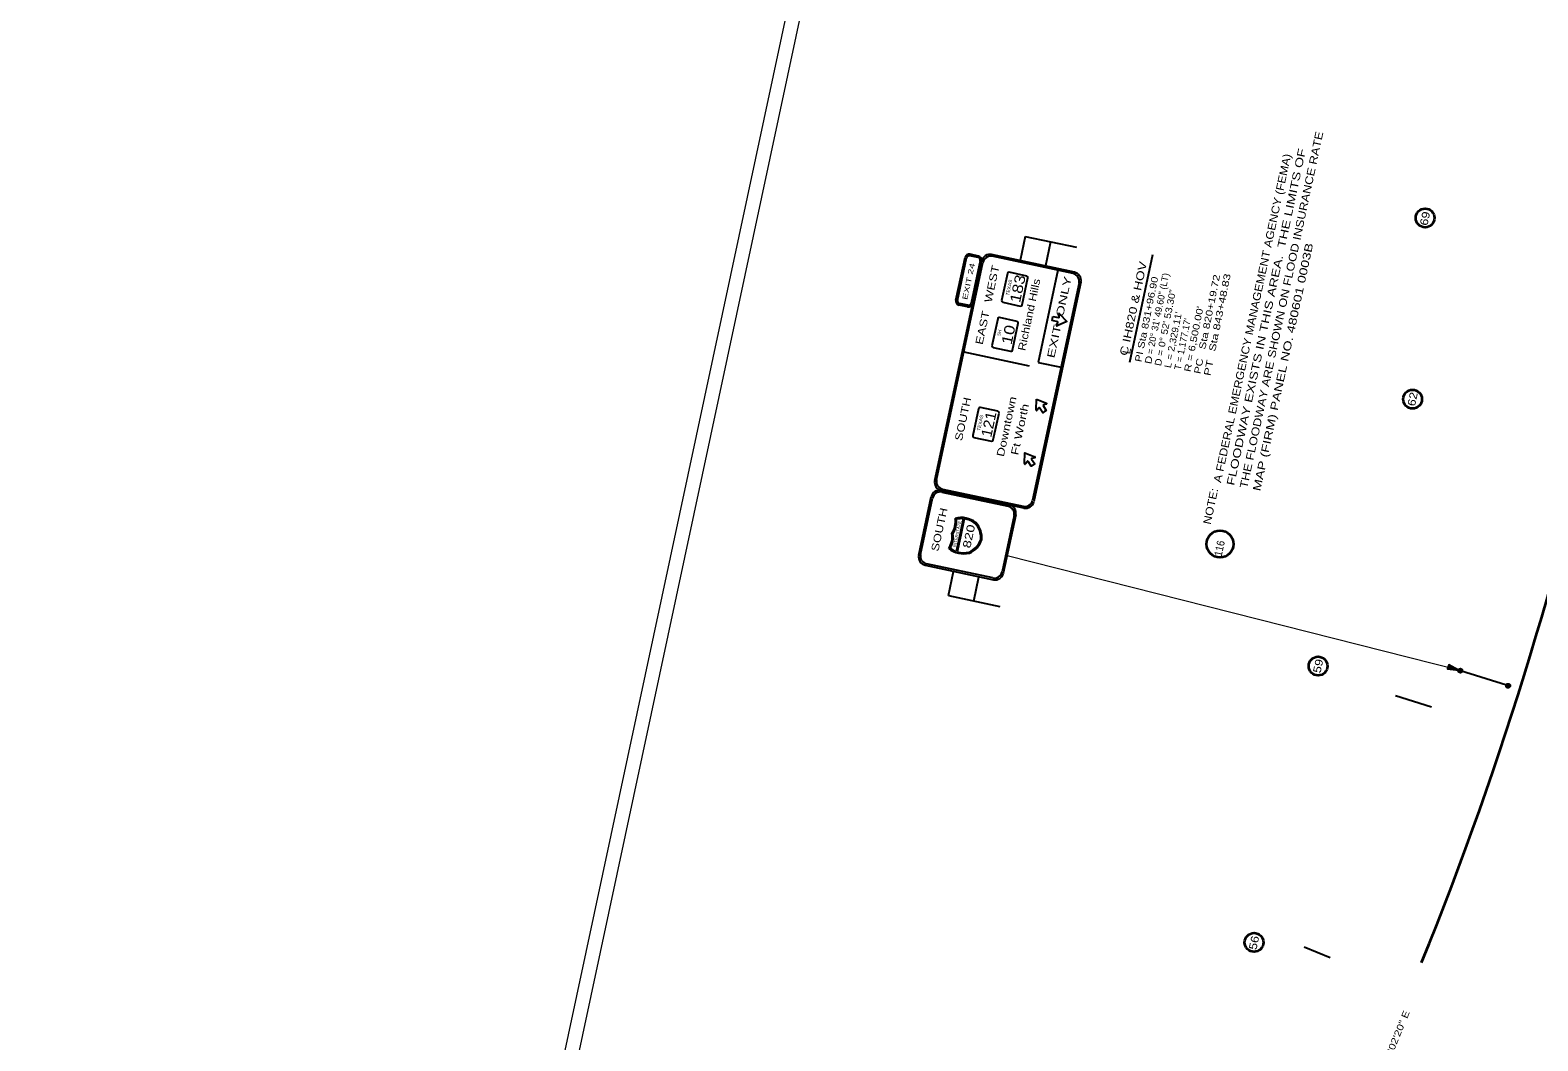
# Model space of a CAD drawing. Extents: x 2363411 to 2369702, y 6977197 to 6988655.
# Drawn here: x 2363411 to 2366110, y 6982449 to 6984259 of the extents above; entities that cross this region are included whole.
import ezdxf
from ezdxf.enums import TextEntityAlignment as Align

# ---------------------------------------------------------------- set-up
doc = ezdxf.new("R2010")
doc.units = 0
doc.header["$LTSCALE"] = 5.6
for name, color, linetype, lineweight in [('1', 7, 'Continuous', 25), ('10', 7, 'Continuous', 13), ('17', 7, 'Continuous', 35), ('23', 7, 'Continuous', 25), ('61', 7, 'Continuous', 25), ('63', 7, 'Continuous', 13)]:
    doc.layers.add(name, color=color, linetype=linetype, lineweight=lineweight)
doc.layers.add('28', color=7, linetype='Continuous')
doc.layers.add('33', color=7, linetype='Continuous')

msp = doc.modelspace()

# ---------------------------------------------------------------- hatches: boundary and pattern name
at = {"layer": '1'}
for points in [[(2365968.163, 6983113.023), (2365950.998, 6983122.363), (2365948.781, 6983115.505)], [(2365974.263, 6983114.727, 1), (2365969.018, 6983109.418, 1)], [(2366059.762, 6983087.598, 1), (2366054.517, 6983082.289, 1)]]:
    msp.add_hatch(color=256, dxfattribs=at).paths.add_polyline_path(points)

# ---------------------------------------------------------------- linework, layer by layer
for p, q in [((2365192.606, 6983889.962), (2365183.395, 6983846.56)), ((2365192.606, 6983889.962), (2365284.591, 6983870.44)), ((2365108.421, 6983851.96), (2365093.308, 6983855.189)), ((2365109.01, 6983854.715), (2365093.895, 6983857.943)), ((2365280.707, 6983825.698), (2365132.568, 6983857.342)), ((2365278.285, 6983823.345), (2365133.814, 6983854.209)), ((2365237.993, 6983880.329), (2365228.781, 6983836.928)), ((2365030.791, 6983452.71), (2365114.777, 6983845.811)), ((2365033.933, 6983453.956), (2365117.108, 6983843.396)), ((2365068.701, 6983775.889), (2365084.996, 6983852.178)), ((2365071.448, 6983775.301), (2365087.743, 6983851.588)), ((2365112.029, 6983846.397), (2365095.724, 6983770.116)), ((2365251.121, 6983829.148), (2365215.907, 6983664.282)), ((2365160.832, 6983823.37), (2365150.543, 6983775.227)), ((2365195.391, 6983818.863), (2365164.167, 6983825.536)), ((2365187.27, 6983767.379), (2365197.551, 6983815.521)), ((2365289.082, 6983806.645), (2365205.903, 6983417.213)), ((2365292.223, 6983807.899), (2365208.262, 6983414.792)), ((2365089.572, 6983763.755), (2365074.466, 6983766.99)), ((2365090.16, 6983766.51), (2365075.054, 6983769.739)), ((2365152.703, 6983771.884), (2365183.927, 6983765.219)), ((2365242.276, 6983746.531), (2365252.428, 6983744.361)), ((2365253.238, 6983745.131), (2365252.478, 6983750.601)), ((2365143.501, 6983742.231), (2365133.221, 6983694.081)), ((2365178.076, 6983737.733), (2365146.837, 6983744.404)), ((2365169.948, 6983686.24), (2365180.228, 6983734.39)), ((2365248.345, 6983731.255), (2365251.289, 6983735.953)), ((2365082.845, 6983682.972), (2365199.745, 6983657.991)), ((2365135.374, 6983690.745), (2365166.605, 6983684.074)), ((2365215.908, 6983664.282), (2365256.808, 6983655.541)), ((2365212.141, 6983579.098), (2365212.873, 6983598.247)), ((2365212.873, 6983598.247), (2365230.661, 6983591.091)), ((2365230.553, 6983589.15), (2365225.149, 6983587.91)), ((2365109.098, 6983581.22), (2365098.803, 6983533.063)), ((2365143.665, 6983576.699), (2365112.434, 6983583.379)), ((2365135.538, 6983525.214), (2365145.833, 6983573.365)), ((2365217.282, 6983582.799), (2365213.951, 6983578.393)), ((2365100.97, 6983529.727), (2365132.202, 6983523.047)), ((2365191.435, 6983483.155), (2365191.445, 6983483.193)), ((2365196.586, 6983486.894), (2365193.256, 6983482.489)), ((2365209.857, 6983493.246), (2365204.453, 6983492.005)), ((2365002.187, 6983318.803), (2365024.526, 6983423.366)), ((2365042.326, 6983434.91), (2365189.62, 6983403.437)), ((2365043.57, 6983431.763), (2365161.915, 6983406.478)), ((2365044.748, 6983437.271), (2365189.213, 6983406.399)), ((2365005.322, 6983320.048), (2365026.879, 6983420.944)), ((2365172.735, 6983389.787), (2365151.178, 6983288.892)), ((2365175.87, 6983391.025), (2365153.53, 6983286.47)), ((2365013.726, 6983301.005), (2365135.74, 6983274.931)), ((2365134.494, 6983278.073), (2365016.133, 6983303.357)), ((2365055.114, 6983246.485), (2365064.445, 6983289.861)), ((2365100.474, 6983236.729), (2365109.804, 6983280.105)), ((2365055.114, 6983246.485), (2365147.045, 6983226.711)), ((2365971.638, 6983112.084), (2366054.42, 6983086.496))]:
    msp.add_line(p, q, dxfattribs=at)
at = {"layer": '1', "lineweight": 13}
msp.add_line((2365968.163, 6983113.023), (2365160.255, 6983317.971), dxfattribs=at)
at = {"layer": '1'}
for points in [[(2365250.852, 6983736.972), (2365240.694, 6983739.133), (2365241.49, 6983742.817), (2365242.276, 6983746.531)], [(2365254.257, 6983751.382), (2365267.28, 6983737.324), (2365249.641, 6983729.807)], [(2365224.738, 6983586.88), (2365230.393, 6983578.17), (2365227.225, 6983576.126), (2365224.044, 6983574.055), (2365218.398, 6983582.77)], [(2365191.445, 6983483.193), (2365192.177, 6983502.342), (2365209.964, 6983495.185)], [(2365204.041, 6983490.975), (2365209.696, 6983482.264), (2365206.529, 6983480.221), (2365203.348, 6983478.151), (2365197.703, 6983486.865)], [(2365081.818, 6983384.265), (2365075.56, 6983354.922), (2365069.278, 6983325.591)], [(2365083.709, 6983384.062), (2365077.402, 6983354.527), (2365071.102, 6983325.008)]]:
    msp.add_lwpolyline(points, dxfattribs=at)
msp.add_lwpolyline([(2365968.163, 6983113.023), (2365950.998, 6983122.363), (2365948.781, 6983115.505)], close=True, dxfattribs=at)
for centre in [(2365971.641, 6983112.073), (2366057.139, 6983084.944)]:
    msp.add_circle(centre, 3.732, dxfattribs=at)
at = {"layer": '1', "lineweight": 35}
msp.add_arc((2359877.328, 6985028.058), 6500, 337.9611, 358.49155, dxfattribs=at)
at = {"layer": '1'}
for centre, radius, start, end in [((2365092.331, 6983850.607), 7.501, 77.93922, 167.93922), ((2365092.331, 6983850.607), 4.688, 77.93922, 167.93922), ((2365107.442, 6983847.378), 7.501, 347.93922, 77.93922), ((2365129.439, 6983842.677), 15.001, 77.93966, 167.93966), ((2365130.881, 6983840.452), 14.063, 77.93966, 167.93966), ((2365107.442, 6983847.378), 4.688, 347.93922, 77.93922), ((2365163.576, 6983822.788), 2.813, 77.93856, 167.93856), ((2365194.803, 6983816.115), 2.813, 347.93856, 77.93856), ((2365275.346, 6983809.587), 14.063, 347.93966, 77.93966), ((2365277.571, 6983811.029), 15.001, 347.93966, 77.93966), ((2365076.032, 6983774.322), 7.501, 167.93922, 257.93922), ((2365076.032, 6983774.322), 4.688, 167.93922, 257.93922), ((2365153.286, 6983774.635), 2.813, 167.93856, 257.93856), ((2365091.142, 6983771.093), 7.501, 257.93922, 347.93922), ((2365091.142, 6983771.093), 4.688, 257.93922, 347.93922), ((2365184.514, 6983767.963), 2.813, 257.93856, 347.93856), ((2365253.493, 6983750.729), 1.012, 42.67816, 188.05929), ((2365146.254, 6983741.649), 2.813, 77.93966, 167.93966), ((2365177.482, 6983734.977), 2.813, 347.93966, 77.93966), ((2365249.22, 6983730.731), 1.012, 147.82003, 293.20117), ((2365250.728, 6983736.309), 0.675, 327.95656, 77.93966), ((2365252.59, 6983745.022), 0.675, 257.93966, 7.92277), ((2365135.966, 6983693.496), 2.813, 167.93966, 257.93966), ((2365167.194, 6983686.824), 2.813, 257.93966, 347.93966), ((2365225.295, 6983587.261), 0.675, 102.95656, 212.93966), ((2365230.304, 6983590.138), 1.012, 282.82003, 68.20117), ((2365111.849, 6983580.628), 2.813, 77.93906, 167.93906), ((2365143.076, 6983573.955), 2.813, 347.93906, 77.93906), ((2365213.143, 6983579.019), 1.012, 177.67816, 323.05929), ((2365217.817, 6983582.416), 0.675, 32.93966, 142.92277), ((2365101.56, 6983532.475), 2.813, 167.93906, 257.93906), ((2365132.788, 6983525.803), 2.813, 257.93906, 347.93906), ((2365192.447, 6983483.114), 1.012, 177.67816, 323.05929), ((2365197.121, 6983486.511), 0.675, 32.93966, 142.92277), ((2365204.599, 6983491.356), 0.675, 102.95656, 212.93966), ((2365209.609, 6983494.234), 1.012, 282.82003, 68.20117), ((2365045.46, 6983449.575), 15.001, 167.93908, 257.93908), ((2365047.685, 6983451.017), 14.063, 167.93908, 257.93908), ((2365039.191, 6983420.236), 15.001, 77.94145, 167.94145), ((2365040.633, 6983418.011), 14.063, 77.94145, 167.94145), ((2365158.981, 6983392.729), 14.063, 347.94145, 77.94145), ((2365161.207, 6983394.171), 15.001, 347.94145, 77.94145), ((2365192.15, 6983420.152), 14.063, 257.93908, 347.93908), ((2365193.592, 6983417.926), 15.001, 257.93908, 347.93908), ((2365031.848, 6983378.537), 35.984, 325.12183, 9.97215), ((2365031.848, 6983378.537), 37.874, 326.31975, 7.31659), ((2365078.505, 6983344.341), 41.954, 51.80463, 105.50701), ((2365078.505, 6983344.341), 40.064, 85.25108, 103.11583), ((2365078.505, 6983344.341), 40.064, 52.02117, 82.53315), ((2365074.513, 6983349.74), 38.808, 355.77949, 42.42587), ((2365074.513, 6983349.74), 40.698, 355.41334, 42.64924), ((2365026.017, 6983351.241), 35.984, 325.91075, 10.76106), ((2365026.017, 6983351.241), 37.874, 328.56631, 9.56315), ((2365076.725, 6983360.091), 38.808, 293.45703, 340.10341), ((2365076.725, 6983360.091), 40.698, 293.23365, 340.46955), ((2365016.852, 6983315.668), 15.001, 167.94145, 257.94145), ((2365019.077, 6983317.11), 14.063, 167.94145, 257.94145), ((2365082.574, 6983363.388), 41.954, 230.37589, 284.07826), ((2365082.574, 6983363.388), 40.064, 232.76706, 250.63182), ((2365082.574, 6983363.388), 40.064, 253.34974, 283.86172), ((2365137.425, 6983291.828), 14.063, 257.94145, 347.94145), ((2365138.867, 6983289.603), 15.001, 257.94145, 347.94145)]:
    msp.add_arc(centre, radius, start, end, dxfattribs=at)
at = {"layer": '10'}
for p, q in [((2363411.416, 6977949.748), (2365605.51, 6988218.434)), ((2363435.864, 6977944.524), (2365629.958, 6988213.21))]:
    msp.add_line(p, q, dxfattribs=at)
at = {"layer": '17'}
for centre, radius in [((2365908.566, 6983922.955), 16.828), ((2365886.091, 6983598.401), 16.828), ((2365541.426, 6983338.805), 24.19), ((2365717.001, 6983120.3), 16.828), ((2365602.381, 6982625.373), 16.828)]:
    msp.add_circle(centre, radius, dxfattribs=at)
at = {"layer": '23'}
for p, q in [((2365920.098, 6983046.404), (2365855.669, 6983067.064)), ((2365738.606, 6982597.628), (2365692.307, 6982616.923))]:
    msp.add_line(p, q, dxfattribs=at)
at = {"layer": '61'}
msp.add_line((2365379.858, 6983664.742), (2365421.093, 6983857.73), dxfattribs=at)

# ---------------------------------------------------------------- texts
at = {"layer": '1'}
for s, height, rotation, width, p in [('EXIT 24', 9.188, 77.939, 1.5, (2365095.754, 6983808.3)), ('WEST', 13.5, 77.939, 1.3, (2365139.52, 6983803.605)), ('Richland Hills', 13.5, 77.94, 1.2, (2365206.336, 6983748.235)), ('EXIT  ONLY', 13.5, 77.939, 1.5, (2365260.273, 6983743.761)), ('EAST', 13.5, 77.939, 1.3, (2365122.733, 6983725.042)), ('SOUTH', 13.5, 77.939, 1.25, (2365087.79, 6983561.447)), ('Downtown', 13.5, 77.94, 1.3, (2365165.768, 6983547.919)), ('Ft Worth', 13.5, 77.94, 1.35, (2365189.724, 6983542.799)), ('SOUTH', 13.5, 77.941, 1.25, (2365045.486, 6983363.485))]:
    msp.add_text(s, height=height, rotation=rotation, dxfattribs=dict(at, width=width)).set_placement(p, align=Align.CENTER)
for s, height, rotation, width, p in [('TEXAS', 6, 77.939, 1.1, (2365163.665, 6983783.506)), ('183', 18.75, 77.939, 1.2, (2365183.261, 6983769.718)), ('10', 18.75, 77.94, 1.25, (2365168.137, 6983694.833)), ('TEXAS', 6, 77.939, 1.1, (2365111.933, 6983541.343)), ('121', 18.75, 77.939, 1.1, (2365131.83, 6983528.941)), ('INTERSTATE', 5.197, 77.941, 1.1, (2365068.435, 6983333.191)), ('820', 14.18, 77.941, 1.35, (2365094.269, 6983330.338))]:
    msp.add_text(s, height=height, rotation=rotation, dxfattribs=dict(at, width=width)).set_placement(p)
msp.add_text('SH', height=6, rotation=77.94, dxfattribs=at).set_placement((2365148.176, 6983710.981))
at = {"layer": '17'}
for s, width, p in [('69', 1.2, (2365915.191, 6983920.461)), ('62', 1.2, (2365892.954, 6983597.022)), ('116', 0.9, (2365547.28, 6983329.685)), ('59', 1.2, (2365723.865, 6983118.924)), ('56', 1.2, (2365609.086, 6982623.253))]:
    msp.add_text(s, height=14, rotation=77.939, dxfattribs=dict(at, width=width)).set_placement(p, align=Align.CENTER)
at = {"layer": '28'}
for s, height, rotation, width, p in [('C IH820 & HOV', 14, 78.048, 1.3, (2365393.074, 6983759.168)), ('N 22°02\'20" E', 12, 67.836, 1.25, (2365857.86, 6982442.388))]:
    msp.add_text(s, height=height, rotation=rotation, dxfattribs=dict(at, width=width)).set_placement(p, align=Align.CENTER)
at = {"layer": '33'}
for s, width, p in [('PI Sta 831+96.90', 1.25, (2365400.434, 6983664.008)), ('Sta 820+19.72', 1.3, (2365515.005, 6983686.657)), ('Sta 843+48.83', 1.35, (2365532.92, 6983683.076)), ('D = 0° 52\' 53.30"', 1.15, (2365435.715, 6983656.956)), ("L = 2,329.11'", 1.1, (2365453.357, 6983653.43)), ("R = 6,500.00'", 1.25, (2365488.639, 6983646.378)), ('D', 1.25, (2365418.075, 6983660.482)), ('PC', 1.25, (2365506.28, 6983642.852)), ('PT', 1.4, (2365523.921, 6983639.326))]:
    msp.add_text(s, height=12, rotation=78.697, dxfattribs=dict(at, width=width)).set_placement(p)
for s, p in [('= 20° 31\' 49.60" (LT)', (2365421.603, 6983678.133)), ("T = 1,177.17'", (2365470.998, 6983649.904))]:
    msp.add_text(s, height=12, rotation=78.697, dxfattribs=at).set_placement(p)
at = {"layer": '61', "width": 1.05}
msp.add_text('L', height=14, rotation=77.939, dxfattribs=at).set_placement((2365381.301, 6983683.738), align=Align.CENTER)
at = {"layer": '63'}
for s, width, p in [('THE FLOODWAY ARE SHOWN ON FLOOD INSURANCE RATE ', 1.2, (2365590.106, 6983437.749)), ('FLOODWAY EXISTS IN THIS AREA.  THE LIMITS OF', 1.35, (2365566.635, 6983442.764)), ('A FEDERAL EMERGENCY MANAGEMENT AGENCY (FEMA)', 1.15, (2365543.164, 6983447.779)), ('MAP (FIRM) PANEL NO. 480601 0003B', 1.35, (2365613.577, 6983432.734))]:
    msp.add_text(s, height=14, rotation=77.939, dxfattribs=dict(at, width=width)).set_placement(p)
at = {"layer": '63', "width": 1.15}
msp.add_text('NOTE:', height=14, rotation=77.939, dxfattribs=at).set_placement((2365531.46, 6983405.177), align=Align.CENTER)

doc.saveas('drawing.dxf')
